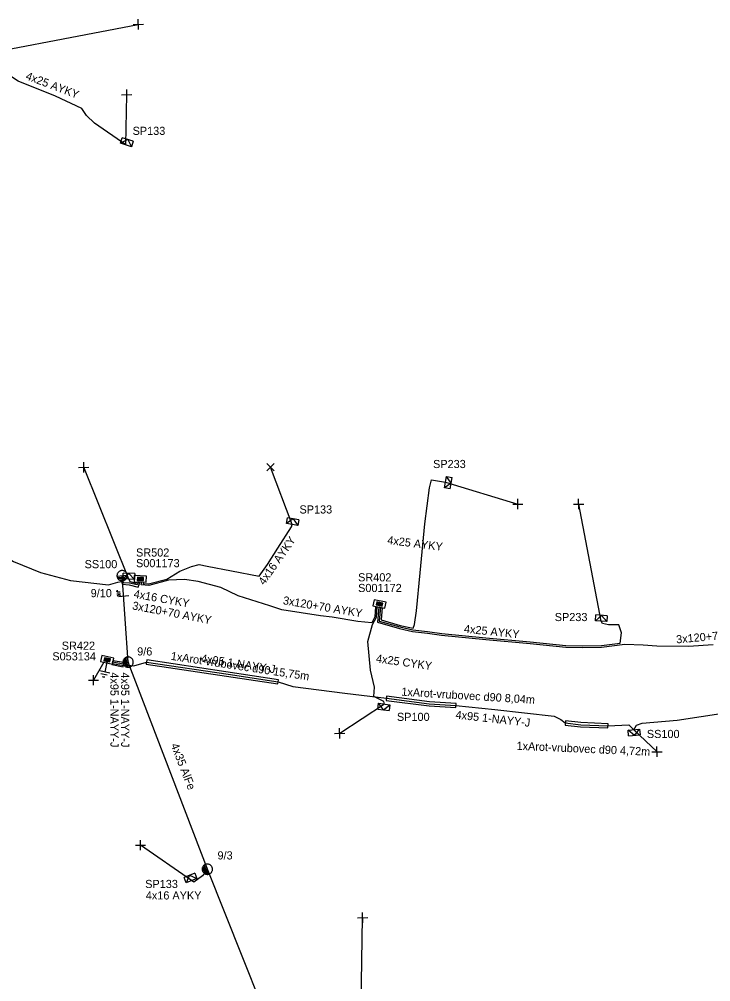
# Model space of a CAD drawing. Extents: x -762504 to -761250, y -1152974 to -1152253.
# Drawn here: x -761531.9 to -761447.4, y -1152391 to -1152273.4 of the extents above; entities that cross this region are included whole.
import ezdxf

# ---------------------------------------------------------------- set-up
doc = ezdxf.new("R2010")
doc.units = 0
for name, color, linetype in [('Vrstva 1', 7, 'Continuous'), ('Vrstva 12', 7, 'Continuous'), ('Vrstva 13', 7, 'Continuous'), ('Vrstva 15', 7, 'Continuous'), ('Vrstva 18', 7, 'Continuous'), ('Vrstva 2', 7, 'Continuous'), ('Vrstva 20', 7, 'Continuous'), ('Vrstva 21', 7, 'Continuous'), ('Vrstva 28', 7, 'Continuous'), ('Vrstva 29', 7, 'Continuous'), ('Vrstva 30', 7, 'Continuous'), ('Vrstva 31', 7, 'Continuous'), ('Vrstva 33', 7, 'Continuous'), ('Vrstva 34', 7, 'Continuous'), ('Vrstva 5', 7, 'Continuous'), ('Vrstva 52', 7, 'Continuous'), ('Vrstva 54', 7, 'Continuous'), ('Vrstva 59', 7, 'Continuous'), ('Vrstva 6', 7, 'Continuous')]:
    doc.layers.add(name, color=color, linetype=linetype)

msp = doc.modelspace()

# ---------------------------------------------------------------- linework, layer by layer
at = {"layer": 'Vrstva 1'}
msp.add_lwpolyline([(-761486.59, -1152433.8), (-761498.04, -1152404.51), (-761508.91, -1152377.22), (-761518.58, -1152351.93), (-761519.32, -1152341.37)], dxfattribs=at)
at = {"layer": 'Vrstva 13'}
for points in [[(-761518.69, -1152341.33), (-761518.698, -1152341.265), (-761518.713, -1152341.2), (-761518.735, -1152341.138), (-761518.762, -1152341.078), (-761518.796, -1152341.022), (-761518.836, -1152340.969), (-761518.881, -1152340.921), (-761518.931, -1152340.878), (-761518.985, -1152340.84), (-761519.043, -1152340.808), (-761519.103, -1152340.782), (-761519.166, -1152340.763), (-761519.231, -1152340.75), (-761519.297, -1152340.744), (-761519.363, -1152340.746), (-761519.428, -1152340.754), (-761519.492, -1152340.769), (-761519.555, -1152340.79), (-761519.614, -1152340.818), (-761519.671, -1152340.852), (-761519.723, -1152340.891), (-761519.772, -1152340.936), (-761519.815, -1152340.986), (-761519.853, -1152341.04), (-761519.885, -1152341.098), (-761519.91, -1152341.158), (-761519.93, -1152341.222), (-761519.942, -1152341.286), (-761519.948, -1152341.352), (-761519.947, -1152341.418), (-761519.939, -1152341.484), (-761519.924, -1152341.548), (-761519.903, -1152341.61), (-761519.875, -1152341.67), (-761519.841, -1152341.726), (-761519.801, -1152341.779), (-761519.756, -1152341.827), (-761519.706, -1152341.87), (-761519.652, -1152341.908), (-761519.595, -1152341.94), (-761519.534, -1152341.966), (-761519.471, -1152341.985), (-761519.406, -1152341.998), (-761519.34, -1152342.004), (-761519.275, -1152342.002), (-761519.209, -1152341.994), (-761519.145, -1152341.98), (-761519.083, -1152341.958), (-761519.023, -1152341.93), (-761518.966, -1152341.896), (-761518.913, -1152341.857), (-761518.865, -1152341.812), (-761518.822, -1152341.762), (-761518.784, -1152341.708), (-761518.752, -1152341.65), (-761518.727, -1152341.59), (-761518.707, -1152341.526), (-761518.695, -1152341.462), (-761518.689, -1152341.396), (-761518.69, -1152341.33)], [(-761519.949, -1152341.414), (-761518.692, -1152341.326)], [(-761519.907, -1152341.589), (-761518.739, -1152341.507)], [(-761519.809, -1152341.73), (-761518.797, -1152341.659)], [(-761519.661, -1152341.868), (-761518.934, -1152341.817)], [(-761518.421, -1152352.54), (-761518.358, -1152352.52), (-761518.298, -1152352.493), (-761518.241, -1152352.46), (-761518.187, -1152352.421), (-761518.138, -1152352.377), (-761518.094, -1152352.328), (-761518.056, -1152352.275), (-761518.023, -1152352.218), (-761517.996, -1152352.158), (-761517.975, -1152352.095), (-761517.962, -1152352.03), (-761517.955, -1152351.965), (-761517.955, -1152351.899), (-761517.962, -1152351.833), (-761517.975, -1152351.769), (-761517.996, -1152351.706), (-761518.023, -1152351.646), (-761518.056, -1152351.588), (-761518.094, -1152351.535), (-761518.138, -1152351.486), (-761518.187, -1152351.442), (-761518.241, -1152351.403), (-761518.298, -1152351.37), (-761518.358, -1152351.344), (-761518.421, -1152351.323), (-761518.485, -1152351.31), (-761518.551, -1152351.303), (-761518.617, -1152351.303), (-761518.682, -1152351.309), (-761518.747, -1152351.323), (-761518.81, -1152351.343), (-761518.87, -1152351.37), (-761518.927, -1152351.403), (-761518.98, -1152351.442), (-761519.029, -1152351.486), (-761519.073, -1152351.535), (-761519.112, -1152351.589), (-761519.145, -1152351.646), (-761519.172, -1152351.706), (-761519.192, -1152351.769), (-761519.206, -1152351.833), (-761519.213, -1152351.899), (-761519.213, -1152351.965), (-761519.206, -1152352.03), (-761519.192, -1152352.095), (-761519.172, -1152352.157), (-761519.145, -1152352.218), (-761519.112, -1152352.275), (-761519.073, -1152352.328), (-761519.029, -1152352.377), (-761518.98, -1152352.421), (-761518.927, -1152352.46), (-761518.87, -1152352.493), (-761518.81, -1152352.52), (-761518.747, -1152352.54), (-761518.682, -1152352.554), (-761518.617, -1152352.561), (-761518.551, -1152352.561), (-761518.485, -1152352.554), (-761518.421, -1152352.54)], [(-761519.027, -1152351.519), (-761518.764, -1152352.498)], [(-761518.907, -1152351.395), (-761518.604, -1152352.526)], [(-761518.744, -1152351.32), (-761518.417, -1152352.537)], [(-761519.134, -1152351.69), (-761518.945, -1152352.393)], [(-761508.677, -1152377.807), (-761508.618, -1152377.779), (-761508.561, -1152377.745), (-761508.508, -1152377.705), (-761508.46, -1152377.66), (-761508.417, -1152377.61), (-761508.379, -1152377.556), (-761508.347, -1152377.499), (-761508.321, -1152377.438), (-761508.302, -1152377.375), (-761508.289, -1152377.31), (-761508.284, -1152377.245), (-761508.285, -1152377.179), (-761508.293, -1152377.113), (-761508.308, -1152377.049), (-761508.329, -1152376.987), (-761508.357, -1152376.927), (-761508.391, -1152376.87), (-761508.431, -1152376.818), (-761508.476, -1152376.77), (-761508.525, -1152376.726), (-761508.579, -1152376.688), (-761508.637, -1152376.656), (-761508.698, -1152376.631), (-761508.761, -1152376.611), (-761508.826, -1152376.599), (-761508.891, -1152376.593), (-761508.957, -1152376.594), (-761509.023, -1152376.602), (-761509.087, -1152376.617), (-761509.149, -1152376.638), (-761509.209, -1152376.666), (-761509.266, -1152376.7), (-761509.318, -1152376.74), (-761509.367, -1152376.785), (-761509.41, -1152376.835), (-761509.447, -1152376.889), (-761509.479, -1152376.946), (-761509.505, -1152377.007), (-761509.525, -1152377.07), (-761509.537, -1152377.135), (-761509.543, -1152377.201), (-761509.542, -1152377.266), (-761509.534, -1152377.332), (-761509.519, -1152377.396), (-761509.497, -1152377.458), (-761509.47, -1152377.518), (-761509.436, -1152377.575), (-761509.396, -1152377.627), (-761509.351, -1152377.676), (-761509.301, -1152377.719), (-761509.247, -1152377.757), (-761509.189, -1152377.789), (-761509.129, -1152377.814), (-761509.066, -1152377.834), (-761509.001, -1152377.846), (-761508.935, -1152377.852), (-761508.869, -1152377.851), (-761508.804, -1152377.843), (-761508.74, -1152377.828), (-761508.677, -1152377.807)], [(-761509.488, -1152377.05), (-761509.216, -1152377.725)], [(-761509.403, -1152376.866), (-761509.023, -1152377.806)], [(-761509.299, -1152376.729), (-761508.861, -1152377.815)], [(-761509.146, -1152376.635), (-761508.674, -1152377.803)]]:
    msp.add_lwpolyline(points, dxfattribs=at)
at = {"layer": 'Vrstva 15'}
for points in [[(-761521.189, -1152351.917), (-761521.449, -1152353.14)], [(-761520.837, -1152353.27), (-761522.06, -1152353.01)], [(-761521.138, -1152353.523), (-761521.908, -1152353.359)], [(-761521.579, -1152353.751), (-761521.704, -1152353.725)], [(-761521.449, -1152353.779), (-761521.579, -1152353.751)]]:
    msp.add_lwpolyline(points, dxfattribs=at)
at = {"layer": 'Vrstva 18'}
for points in [[(-761519.973, -1152343.295), (-761519.945, -1152343.219)], [(-761519.97, -1152343.325), (-761519.973, -1152343.295)], [(-761519.93, -1152343.39), (-761519.97, -1152343.325)], [(-761519.945, -1152343.219), (-761519.892, -1152343.199)], [(-761519.874, -1152343.405), (-761519.93, -1152343.39)], [(-761519.892, -1152343.199), (-761519.843, -1152343.195)], [(-761519.551, -1152343.377), (-761519.874, -1152343.405)], [(-761519.533, -1152343.583), (-761519.945, -1152343.619)], [(-761519.698, -1152343.666), (-761519.924, -1152343.859)], [(-761519.788, -1152343.605), (-761519.515, -1152343.789)], [(-761518.503, -1152343.829), (-761519.749, -1152343.938)]]:
    msp.add_lwpolyline(points, dxfattribs=at)
at = {"layer": 'Vrstva 20'}
for points in [[(-761516.29, -1152351.67), (-761516.37, -1152352.17), (-761500.3, -1152354.58), (-761500.22, -1152354.08)], [(-761519.1, -1152351.99), (-761520.46, -1152351.76), (-761520.58, -1152352.24), (-761519.18, -1152352.49)], [(-761487.02, -1152356.1), (-761487.07, -1152356.6), (-761481.83, -1152357.28), (-761478.58, -1152357.48), (-761478.52, -1152356.98), (-761481.79, -1152356.78)], [(-761465.18, -1152359.11), (-761465.22, -1152359.61), (-761463.34, -1152359.82), (-761460.01, -1152359.97), (-761459.98, -1152359.47), (-761463.3, -1152359.32)]]:
    msp.add_lwpolyline(points, close=True, dxfattribs=at)
at = {"layer": 'Vrstva 28'}
for points in [[(-761517.836, -1152341.368), (-761517.862, -1152342.117)], [(-761517.862, -1152342.117), (-761516.363, -1152342.17)], [(-761516.336, -1152341.42), (-761517.836, -1152341.368)], [(-761517.459, -1152341.57), (-761517.472, -1152341.948)], [(-761517.472, -1152341.948), (-761516.728, -1152341.974)], [(-761516.715, -1152341.596), (-761517.459, -1152341.57)], [(-761517.413, -1152341.619), (-761517.423, -1152341.902)], [(-761517.423, -1152341.902), (-761516.774, -1152341.925)], [(-761516.764, -1152341.641), (-761517.413, -1152341.619)], [(-761517.367, -1152341.668), (-761517.374, -1152341.857)], [(-761517.374, -1152341.857), (-761516.819, -1152341.876)], [(-761516.813, -1152341.687), (-761517.367, -1152341.668)], [(-761517.322, -1152341.717), (-761517.325, -1152341.811)], [(-761517.325, -1152341.811), (-761516.865, -1152341.827)], [(-761516.861, -1152341.733), (-761517.322, -1152341.717)], [(-761516.904, -1152341.778), (-761517.282, -1152341.765)], [(-761516.865, -1152341.827), (-761516.861, -1152341.733)], [(-761516.819, -1152341.876), (-761516.813, -1152341.687)], [(-761516.774, -1152341.925), (-761516.764, -1152341.641)], [(-761516.728, -1152341.974), (-761516.715, -1152341.596)], [(-761516.363, -1152342.17), (-761516.336, -1152341.42)], [(-761488.556, -1152344.324), (-761488.699, -1152345.06)], [(-761487.083, -1152344.61), (-761488.556, -1152344.324)], [(-761488.215, -1152344.582), (-761488.287, -1152344.953)], [(-761487.485, -1152344.724), (-761488.215, -1152344.582)], [(-761487.227, -1152345.346), (-761487.083, -1152344.61)], [(-761488.699, -1152345.06), (-761487.227, -1152345.346)], [(-761488.287, -1152344.953), (-761487.557, -1152345.095)], [(-761488.178, -1152344.638), (-761488.232, -1152344.916)], [(-761488.232, -1152344.916), (-761487.594, -1152345.04)], [(-761487.54, -1152344.762), (-761488.178, -1152344.638)], [(-761488.14, -1152344.693), (-761488.176, -1152344.879)], [(-761488.176, -1152344.879), (-761487.632, -1152344.985)], [(-761487.595, -1152344.799), (-761488.14, -1152344.693)], [(-761488.103, -1152344.749), (-761488.121, -1152344.841)], [(-761488.121, -1152344.841), (-761487.669, -1152344.929)], [(-761487.651, -1152344.837), (-761488.103, -1152344.749)], [(-761487.7, -1152344.875), (-761488.071, -1152344.803)], [(-761487.669, -1152344.929), (-761487.651, -1152344.837)], [(-761487.632, -1152344.985), (-761487.595, -1152344.799)], [(-761487.594, -1152345.04), (-761487.54, -1152344.762)], [(-761487.557, -1152345.095), (-761487.485, -1152344.724)], [(-761521.791, -1152351.131), (-761521.947, -1152351.865)], [(-761520.324, -1152351.443), (-761521.791, -1152351.131)], [(-761521.465, -1152351.388), (-761521.544, -1152351.757)], [(-761521.429, -1152351.444), (-761521.488, -1152351.721)], [(-761520.737, -1152351.542), (-761521.465, -1152351.388)], [(-761521.392, -1152351.5), (-761521.432, -1152351.685)], [(-761520.793, -1152351.579), (-761521.429, -1152351.444)], [(-761520.849, -1152351.615), (-761521.392, -1152351.5)], [(-761521.356, -1152351.556), (-761521.376, -1152351.648)], [(-761521.376, -1152351.648), (-761520.925, -1152351.744)], [(-761520.905, -1152351.652), (-761521.356, -1152351.556)], [(-761521.325, -1152351.611), (-761520.956, -1152351.689)], [(-761520.925, -1152351.744), (-761520.905, -1152351.652)], [(-761520.889, -1152351.8), (-761520.849, -1152351.615)], [(-761520.852, -1152351.856), (-761520.793, -1152351.579)], [(-761520.816, -1152351.912), (-761520.737, -1152351.542)], [(-761520.48, -1152352.177), (-761520.324, -1152351.443)], [(-761521.947, -1152351.865), (-761520.48, -1152352.177)], [(-761521.544, -1152351.757), (-761520.816, -1152351.912)], [(-761521.488, -1152351.721), (-761520.852, -1152351.856)], [(-761521.432, -1152351.685), (-761520.889, -1152351.8)]]:
    msp.add_lwpolyline(points, dxfattribs=at)
at = {"layer": 'Vrstva 31'}
for points in [[(-761517.975, -1152288.321), (-761518.191, -1152288.987), (-761519.523, -1152288.554), (-761519.307, -1152287.888)], [(-761518.641, -1152288.105), (-761519.523, -1152288.554)], [(-761517.975, -1152288.321), (-761519.307, -1152287.888)], [(-761518.641, -1152288.105), (-761518.191, -1152288.987)], [(-761479.252, -1152330.754), (-761479.942, -1152330.632), (-761479.699, -1152329.254), (-761479.009, -1152329.375)], [(-761479.131, -1152330.064), (-761479.699, -1152329.254)], [(-761479.131, -1152330.064), (-761479.942, -1152330.632)], [(-761479.252, -1152330.754), (-761479.009, -1152329.375)], [(-761497.726, -1152334.562), (-761497.848, -1152335.252), (-761499.226, -1152335.009), (-761499.105, -1152334.319)], [(-761498.415, -1152334.441), (-761499.226, -1152335.009)], [(-761497.726, -1152334.562), (-761499.105, -1152334.319)], [(-761498.415, -1152334.441), (-761497.848, -1152335.252)], [(-761517.783, -1152341.125), (-761517.807, -1152341.824), (-761519.207, -1152341.775), (-761519.182, -1152341.076)], [(-761517.783, -1152341.125), (-761519.182, -1152341.076)], [(-761518.483, -1152341.1), (-761519.207, -1152341.775)], [(-761518.483, -1152341.1), (-761517.807, -1152341.824)], [(-761460.07, -1152346.27), (-761460.119, -1152346.969), (-761461.515, -1152346.871), (-761461.467, -1152346.173)], [(-761460.768, -1152346.222), (-761461.515, -1152346.871)], [(-761460.07, -1152346.27), (-761461.467, -1152346.173)], [(-761460.768, -1152346.222), (-761460.119, -1152346.969)], [(-761488.103, -1152357.656), (-761488.006, -1152356.963), (-761486.62, -1152357.158), (-761486.717, -1152357.851)], [(-761487.41, -1152357.753), (-761488.006, -1152356.963)], [(-761487.41, -1152357.753), (-761486.62, -1152357.158)], [(-761488.103, -1152357.656), (-761486.717, -1152357.851)], [(-761457.469, -1152360.949), (-761457.53, -1152360.251), (-761456.135, -1152360.129), (-761456.074, -1152360.827)], [(-761456.771, -1152360.888), (-761457.53, -1152360.251)], [(-761457.469, -1152360.949), (-761456.074, -1152360.827)], [(-761456.771, -1152360.888), (-761456.135, -1152360.129)], [(-761510.451, -1152377.697), (-761511.749, -1152378.222)], [(-761510.451, -1152377.697), (-761510.188, -1152378.346), (-761511.486, -1152378.871), (-761511.749, -1152378.222)], [(-761511.1, -1152377.96), (-761511.486, -1152378.871)], [(-761511.1, -1152377.96), (-761510.188, -1152378.346)]]:
    msp.add_lwpolyline(points, dxfattribs=at)
at = {"layer": 'Vrstva 34'}
for points in [[(-761517.965, -1152274.051), (-761516.715, -1152274.029)], [(-761517.329, -1152274.665), (-761517.351, -1152273.415)], [(-761518.739, -1152283.255), (-761518.761, -1152282.005)], [(-761519.375, -1152282.641), (-761518.125, -1152282.619)], [(-761524.625, -1152328.141), (-761523.375, -1152328.119)], [(-761523.989, -1152328.755), (-761524.011, -1152327.505)], [(-761501.632, -1152327.688), (-761500.748, -1152328.572)], [(-761501.632, -1152328.572), (-761500.748, -1152327.688)], [(-761471.625, -1152332.641), (-761470.375, -1152332.619)], [(-761470.989, -1152333.255), (-761471.011, -1152332.005)], [(-761464.185, -1152332.641), (-761462.935, -1152332.619)], [(-761463.549, -1152333.255), (-761463.571, -1152332.005)], [(-761522.799, -1152354.755), (-761522.821, -1152353.505)], [(-761523.435, -1152354.141), (-761522.185, -1152354.119)], [(-761493.375, -1152360.641), (-761492.125, -1152360.619)], [(-761492.739, -1152361.255), (-761492.761, -1152360.005)], [(-761453.989, -1152363.505), (-761454.011, -1152362.255)], [(-761454.625, -1152362.891), (-761453.375, -1152362.869)], [(-761517.059, -1152374.905), (-761517.081, -1152373.655)], [(-761517.695, -1152374.291), (-761516.445, -1152374.269)], [(-761490.575, -1152383.151), (-761489.325, -1152383.129)], [(-761489.939, -1152383.765), (-761489.961, -1152382.515)]]:
    msp.add_lwpolyline(points, dxfattribs=at)
at = {"layer": 'Vrstva 5'}
for points in [[(-761518.86, -1152288.77), (-761522.69, -1152286.1), (-761523.66, -1152285.17), (-761524.24, -1152284.3), (-761527.44, -1152282.79), (-761532.03, -1152280.96), (-761533.66, -1152279.92), (-761536.57, -1152277.67), (-761537.9, -1152276.88), (-761539.08, -1152276.05), (-761539.78, -1152275.86), (-761542.08, -1152278.31), (-761544.06, -1152280.96), (-761545.65, -1152282.98), (-761546.96, -1152284.58), (-761546.86, -1152284.73)], [(-761551.64, -1152328.87), (-761551.77, -1152329.2), (-761550.31, -1152330.15), (-761547.72, -1152331.96), (-761543.14, -1152334.7), (-761538.27, -1152337.24), (-761533.97, -1152338.75), (-761532.59, -1152339.66), (-761529.29, -1152340.97), (-761525.62, -1152341.97), (-761521, -1152342.51), (-761519.85, -1152342.17), (-761519.4, -1152342.07), (-761519.32, -1152342.41), (-761518.44, -1152342.5), (-761517.37, -1152342.76), (-761517.11, -1152342.14)], [(-761487.56, -1152345.24), (-761487.7, -1152346.77), (-761485.36, -1152347.44), (-761483.76, -1152347.79), (-761483.61, -1152347.34), (-761483.39, -1152345.66), (-761482.94, -1152341.04), (-761482.34, -1152335.03), (-761481.78, -1152330.65), (-761481.52, -1152329.67), (-761479.82, -1152329.94)], [(-761516.71, -1152342.16), (-761516.74, -1152342.31), (-761516.09, -1152342.37), (-761513.87, -1152341.79), (-761512.27, -1152340.81), (-761510.83, -1152340.25), (-761509.9, -1152340.01), (-761508.94, -1152340.21), (-761505.97, -1152340.78), (-761502.57, -1152341.42), (-761501.57, -1152340.02), (-761500.3, -1152338), (-761498.65, -1152335.39), (-761498.54, -1152335.13)], [(-761517.31, -1152342.13), (-761517.49, -1152342.51), (-761518.41, -1152342.3), (-761519.15, -1152342.23), (-761519.32, -1152341.37)], [(-761518.51, -1152341.8), (-761518.38, -1152342.1), (-761517.59, -1152342.29), (-761517.51, -1152342.13)], [(-761488.36, -1152345.16), (-761488.47, -1152346.4), (-761488.83, -1152347.15), (-761490.55, -1152346.95), (-761493.68, -1152346.44), (-761495.08, -1152346.26), (-761499.83, -1152345.54), (-761501.28, -1152345.07), (-761505.14, -1152343.85), (-761507.25, -1152342.83), (-761510.04, -1152342.07), (-761511.72, -1152341.84), (-761513.67, -1152341.94), (-761516.07, -1152342.57), (-761517.01, -1152342.49), (-761516.91, -1152342.15)], [(-761487.29, -1152357.07), (-761487.35, -1152356.75), (-761488.57, -1152356.14), (-761488.48, -1152355), (-761488.97, -1152352.93), (-761489.32, -1152349.4), (-761488.75, -1152347.33), (-761488.27, -1152346.42), (-761488.16, -1152345.18)], [(-761487.96, -1152345.2), (-761488.14, -1152347.06), (-761485.46, -1152347.82), (-761483.86, -1152348.18), (-761482.04, -1152348.39), (-761480.3, -1152348.63), (-761474.91, -1152349.18), (-761469.51, -1152349.65), (-761465.14, -1152350.11), (-761463.16, -1152350.15), (-761460.78, -1152350.1), (-761457.93, -1152349.73), (-761455.7, -1152349.82), (-761454.03, -1152349.94), (-761450.14, -1152349.98), (-761447.16, -1152349.78)], [(-761487.76, -1152345.22), (-761487.91, -1152346.92), (-761485.41, -1152347.63), (-761483.82, -1152347.98), (-761482.01, -1152348.19), (-761480.28, -1152348.43), (-761474.89, -1152348.98), (-761469.49, -1152349.45), (-761465.12, -1152349.91), (-761463.16, -1152349.95), (-761460.8, -1152349.9), (-761458.51, -1152349.61), (-761458.32, -1152348.35), (-761458.67, -1152347.38), (-761459.94, -1152347.37), (-761460.64, -1152347.22), (-761460.82, -1152346.92)], [(-761520.48, -1152352.11), (-761519.16, -1152352.34), (-761518.59, -1152352.3), (-761517.9, -1152352.38), (-761516.33, -1152351.92), (-761506.36, -1152353.42), (-761500.26, -1152354.33), (-761498.48, -1152354.91), (-761492.14, -1152355.74), (-761487.05, -1152356.35), (-761481.81, -1152357.03), (-761478.56, -1152357.23), (-761473.81, -1152357.7), (-761466.57, -1152358.55), (-761465.74, -1152358.95), (-761465.21, -1152359.36), (-761463.32, -1152359.57), (-761460, -1152359.72), (-761457.46, -1152359.57), (-761456.83, -1152360.19), (-761456.52, -1152359.61), (-761455.81, -1152359.4), (-761451.55, -1152359.02), (-761445.67, -1152358.12)], [(-761520.44, -1152351.91), (-761519, -1152352.16), (-761518.58, -1152351.93)]]:
    msp.add_lwpolyline(points, dxfattribs=at)
at = {"layer": 'Vrstva 52'}
msp.add_lwpolyline([(-761508.91, -1152377.22), (-761509.52, -1152378.04), (-761510.55, -1152378.81), (-761510.84, -1152378.61)], dxfattribs=at)
at = {"layer": 'Vrstva 59'}
for points in [[(-761545.39, -1152282.93), (-761542.09, -1152278.79), (-761517.34, -1152274.04)], [(-761518.86, -1152288.77), (-761518.75, -1152282.63)], [(-761518.51, -1152341.8), (-761524, -1152328.13)], [(-761498.54, -1152335.13), (-761501.19, -1152328.13)], [(-761479.82, -1152329.94), (-761471, -1152332.63)], [(-761460.82, -1152346.92), (-761463.56, -1152332.63)], [(-761521.56, -1152351.94), (-761522.81, -1152354.13)], [(-761487.29, -1152357.07), (-761492.75, -1152360.63)], [(-761456.83, -1152360.19), (-761454, -1152362.88)], [(-761510.84, -1152378.61), (-761517.07, -1152374.28)], [(-761490.24, -1152401.61), (-761489.95, -1152383.14)]]:
    msp.add_lwpolyline(points, dxfattribs=at)

# ---------------------------------------------------------------- texts
at = {"layer": 'Vrstva 12'}
for s, p in [('9/10', (-761523.16, -1152344)), ('9/6', (-761517.48, -1152351.12)), ('9/3', (-761507.67, -1152376.03))]:
    msp.add_text(s, height=0.9943, dxfattribs=at).set_placement(p)
at = {"layer": 'Vrstva 2'}
msp.add_text('4x35 AlFe', height=0.9943, rotation=291.17389, dxfattribs=at).set_placement((-761513.4, -1152362.05))
at = {"layer": 'Vrstva 21'}
for s, height, rotation, p in [('1xArot-vrubovec d90 15,75m', 0.99429, 351.47098, (-761513.42, -1152351.64)), ('1xArot-vrubovec d90 8,04m', 0.99428, 356.47505, (-761485.24, -1152356.02)), ('1xArot-vrubovec d90 4,72m', 0.99428, 357.4162, (-761471.17, -1152362.63))]:
    msp.add_text(s, height=height, rotation=rotation, dxfattribs=at).set_placement(p)
at = {"layer": 'Vrstva 29'}
for s, p in [('S001173', (-761517.62, -1152340.34)), ('S001172', (-761490.5, -1152343.37)), ('S053134', (-761527.84, -1152351.72))]:
    msp.add_text(s, height=0.9943, dxfattribs=at).set_placement(p)
at = {"layer": 'Vrstva 30'}
for s, p in [('SR502', (-761517.62, -1152339.04)), ('SR402', (-761490.5, -1152342.07)), ('SR422', (-761526.69, -1152350.42))]:
    msp.add_text(s, height=0.9943, dxfattribs=at).set_placement(p)
at = {"layer": 'Vrstva 33'}
for s, p in [('SP133', (-761518.04, -1152287.54)), ('SP233', (-761481.35, -1152328.23)), ('SP133', (-761497.66, -1152333.78)), ('SS100', (-761523.9, -1152340.46)), ('SP233', (-761466.49, -1152346.92)), ('SP100', (-761485.76, -1152359.11)), ('SS100', (-761455.24, -1152361.2)), ('SP133', (-761516.5, -1152379.52))]:
    msp.add_text(s, height=0.9943, dxfattribs=at).set_placement(p)
at = {"layer": 'Vrstva 54'}
msp.add_text('4x16 AYKY', height=0.9943, dxfattribs=at).set_placement((-761516.43, -1152380.92))
at = {"layer": 'Vrstva 6'}
for s, height, rotation, p in [('4x25 AYKY', 0.9943, 339.3392, (-761531.18, -1152280.73)), ('4x16 AYKY', 0.9943, 55.06138, (-761501.96, -1152342.6)), ('4x25 AYKY', 0.9943, 352.75194, (-761486.98, -1152337.49)), ('4x16 CYKY', 0.9943, 349.90435, (-761517.96, -1152344.05)), ('3x120+70 AYKY', 0.99429, 349.28293, (-761518.14, -1152345.48)), ('3x120+70 AYKY', 0.99429, 350.49323, (-761499.73, -1152344.85)), ('4x25 AYKY', 0.9943, 354.11401, (-761477.61, -1152348.33)), ('3x120+70 AYKY', 0.99429, 5.07427, (-761451.62, -1152349.65)), ('4x95 1-NAYY-J', 0.99428, 351.44394, (-761509.74, -1152351.93)), ('4x25 CYKY', 0.9943, 352.07257, (-761488.36, -1152351.95)), ('4x95 1-NAYY-J', 0.99429, 270, (-761520.75, -1152353.18)), ('4x95 1-NAYY-J', 0.99429, 270, (-761519.44, -1152353.18)), ('4x95 1-NAYY-J', 0.99429, 353.64326, (-761478.64, -1152358.82))]:
    msp.add_text(s, height=height, rotation=rotation, dxfattribs=at).set_placement(p)

doc.saveas('drawing.dxf')
